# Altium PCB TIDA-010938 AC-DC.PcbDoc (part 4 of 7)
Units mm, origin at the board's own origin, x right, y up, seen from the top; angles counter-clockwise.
Board outline 275 x 170 mm, 4 copper layers (Top Layer, Layer 1, Layer 2, Bottom Layer), stack 1.787 mm thick; 711 components, 426 nets, 2196 pads, 1444 vias.
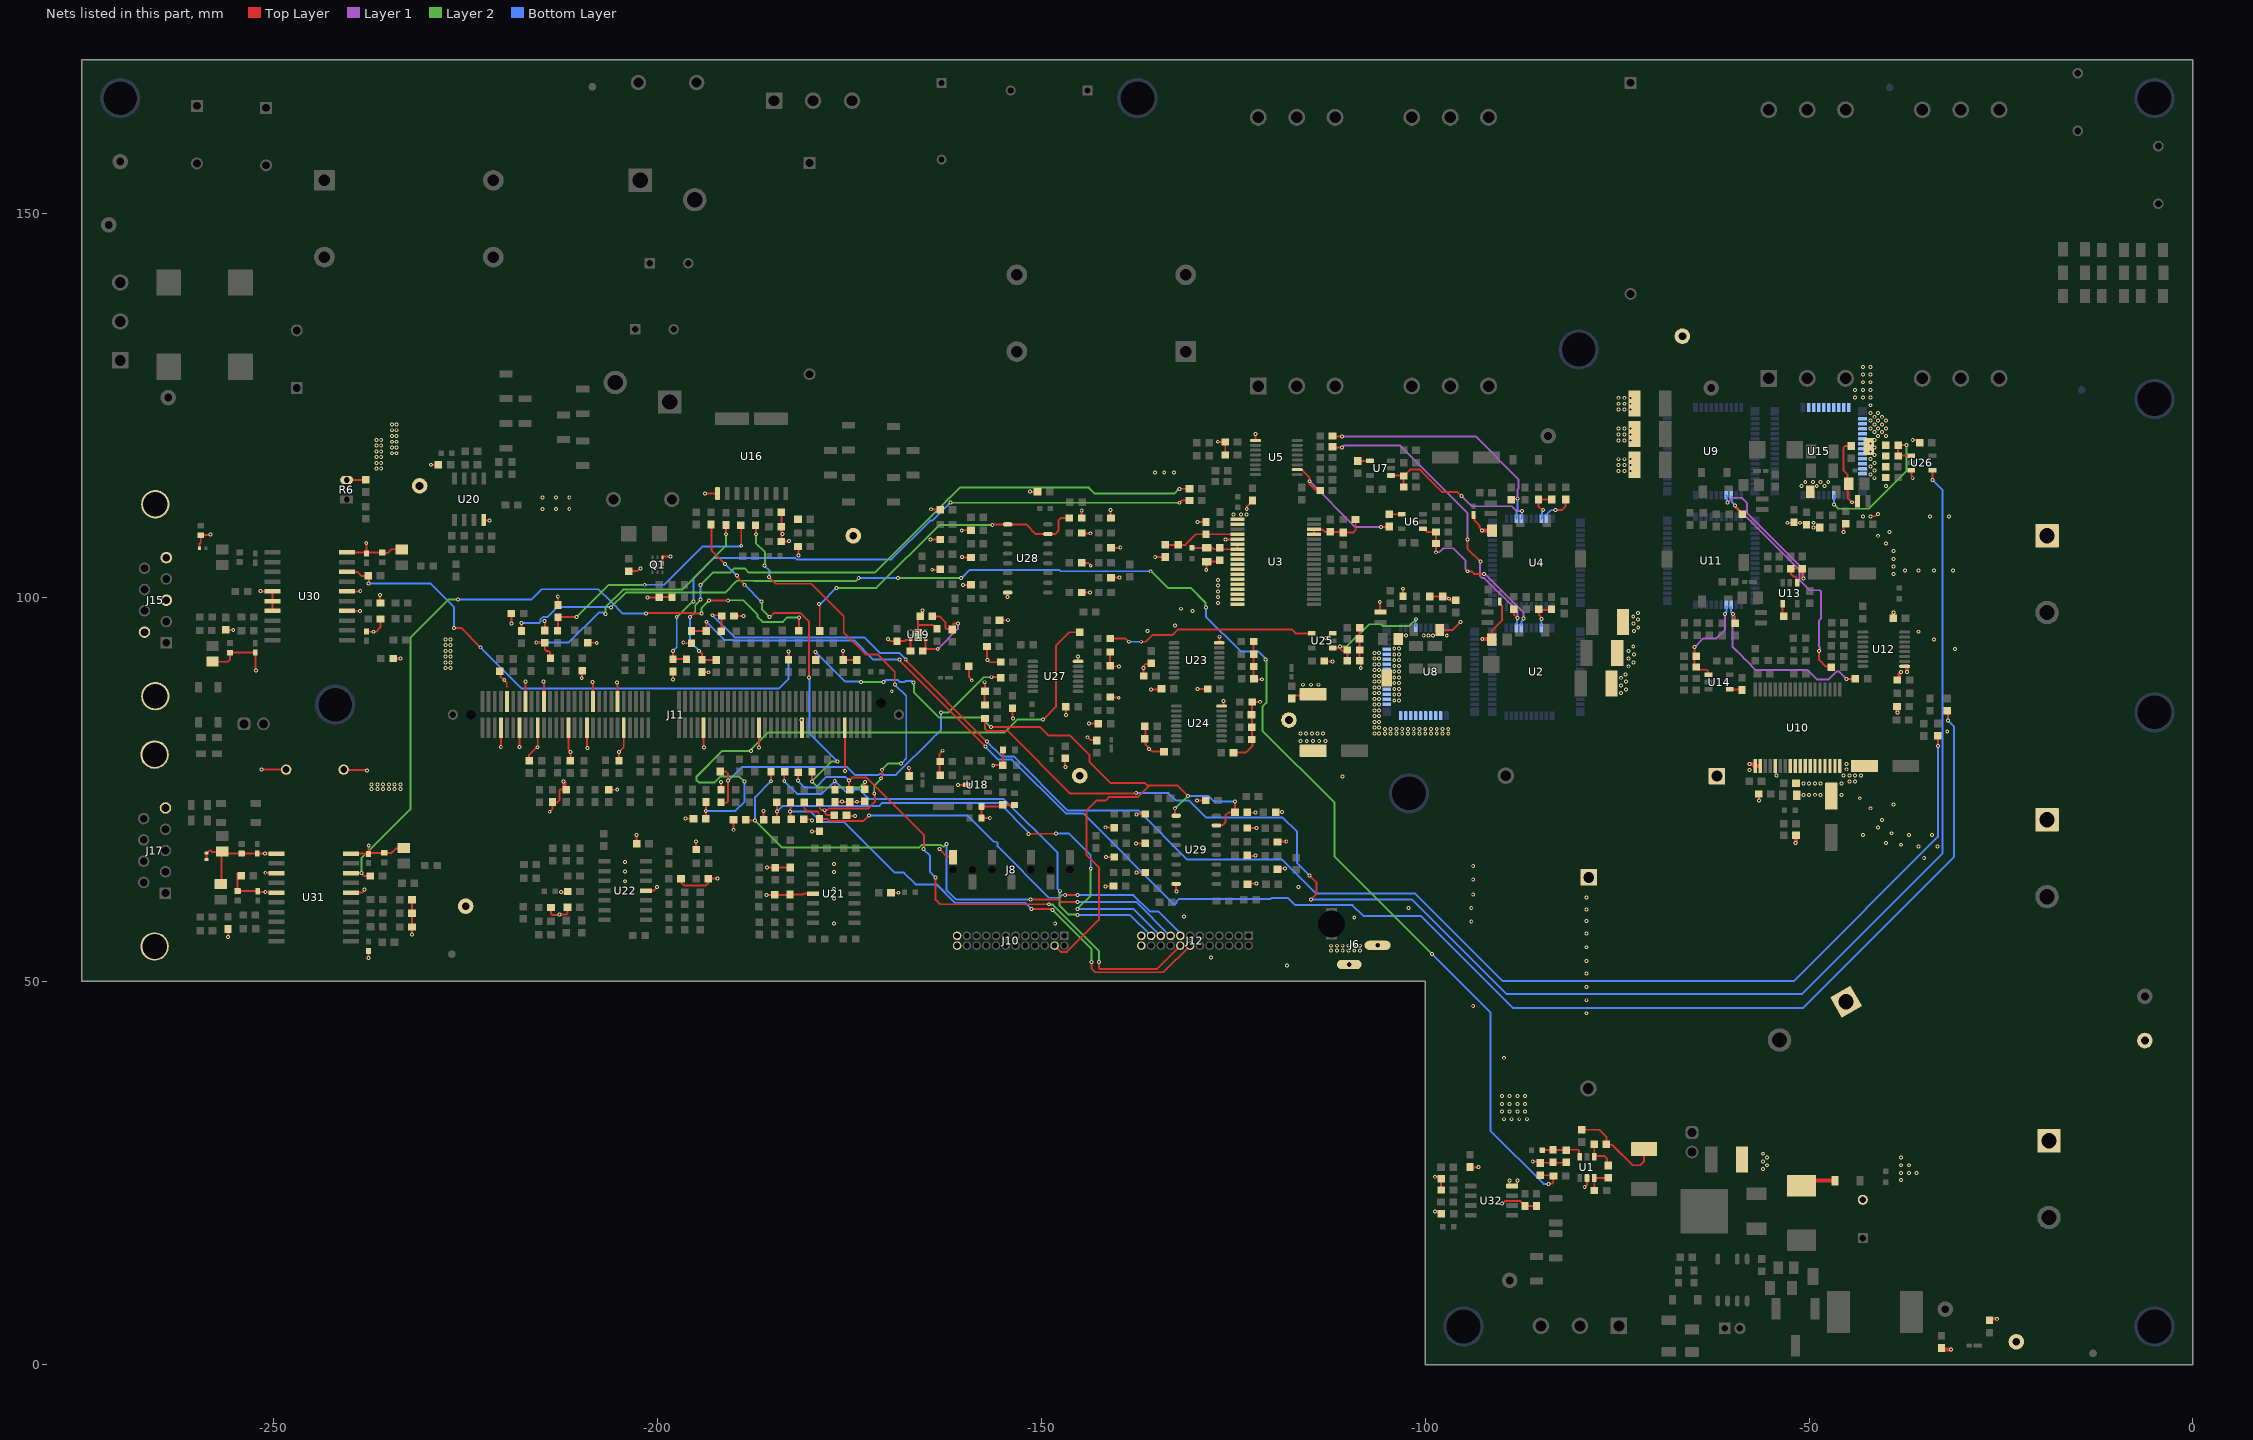
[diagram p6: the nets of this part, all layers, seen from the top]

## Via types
v1: diameter 0.508, hole 0.254, Top Layer to Bottom Layer, tented both sides, 1436 vias
v2: diameter 0.508, hole 0.254, Top Layer to Bottom Layer, 6 vias
v3: diameter 0.5, hole 0.2, Top Layer to Bottom Layer, 2 vias

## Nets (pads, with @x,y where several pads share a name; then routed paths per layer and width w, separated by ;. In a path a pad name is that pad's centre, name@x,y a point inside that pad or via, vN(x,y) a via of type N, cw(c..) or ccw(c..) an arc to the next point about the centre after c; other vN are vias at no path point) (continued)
"DC Bus-": C1.2 C2.1 C3.1 C4.1 C5.1 C6.2 C7.2 C9.1 C10.2 C18.1 C22.2 C23.1 C29.1 C30.2 C31.2 C36.1 C37.1 C38.2 C41.1 C42.1 C46.2 C49.2 C50.1 C51.1 C52.1 C53.1 C54.2 C55.2 C56.1 C64.1 C67.2 C68.1 C74.1 C76.2 C82.1 C83.1 C84.2 C86.1 C87.1 C88.2 C90.2 C92.1 C93.1 C94.2 C95.1 C96.1 C97.1 C98.1 C99.2 C100.1 C101.1 C105.2 C107.1 C108.1 C109.2 C110.2 C111.2 C112.1 C113.1 C114.2 C115.2 C118.2 C119.2 C120.2 C121.2 C122.2 C123.2 C124.2 C125.1 C126.2 C127.1 C128.1 C130.1 C131.1 C132.1 C133.1 C134.1 C135.1 C136.1 C137.1 C138.1 C139.1 C140.1 C141.1 C142.1 C145.1 C146.1 C150.2 C151.1 C152.1 C156.2 C157.1 C158.1 C161.1 C162.2 C163.1 C164.1 C165.1 C167.1 C168.1 C169.2 C170.1 C171.1 C172.1 C173.1 C174.1 C175.1 C176.2 C177.1 C178.1 C179.1 C180.1 C181.1 C182.2 C185.2 C186.2 C187.1 C189.1 C190.1 C191.2 C192.1 C193.1 C194.1 C195.2 C196.1 C197.2 C199.1 C200.1 C201.2 C202.1 C203.2 C204.1 C206.1 C208.1 C209.1 C214.1 C215.2 C216.2 C218.1 C219.1 C222.2 C229.2 C230.1 C231.1 C232.1 C234.1 C235.1 C238.2 C239.2 C241.1 C242.1 C251.2 C252.2 C253.1 C254.1 C255.1 C256.1 D19.2 D20.2 J6.2 J6.3 J8.7 J10.23 J10.24 J11.7 J11.10 J11.13 J11.16 J11.19 J11.22 J11.29 J11.35 J11.38 J11.46 J11.47 J11.65 J11.83 J11.97 J11.111 J12.23 J12.24 L5.1 L9.1 Q1.4 Q1.7 R1.2 R4.1 R6.2 R14.1 R16.1 R40.1 R43.1 R48.1 R50.2 R70.1 R74.1 R76.1 R90.2 R92.1 R100.2 R101.1 R102.1 R106.2 R107.1 R110.2 R115.1 R135.2 R147.1 R157.1 R167.1 R172.2 R177.1 R202.1 R252.1 R253.1 R254.1 R255.1 R256.1 R258.1 R297.1 R298.1 R299.1 R300.1 R301.1 R302.1 R303.1 R304.1 R305.1 R306.1 R307.1 R308.1 R335.1 R336.1 R337.1 R338.1 TP2.1 TP3.1 TP6.1 TP8.1 TP9.1 TP11.1 TP12.1 TP16.1 TP21.1 TP22.1 U1.2 U3.1 U3.2 U3.5 U3.8 U3.9 U3.10 U3.11 U3.12 U3.13 U3.14 U3.15 U3.16 U3.17 U3.18 U5.9 U8.18 U8.19 U8.20 U8.21 U8.22 U8.23 U8.24 U8.25 U8.26 U8.28 U8.29 U8.30 U8.31 U8.32 U8.33 U8.34 U8.35 U8.36 U8.37 U8.38 U8.39 U10.1 U10.2 U10.5 U10.8 U10.9 U10.10 U10.11 U10.12 U10.13 U10.14 U10.15 U10.16 U10.17 U10.18 U12.9 U15.18 U15.19 U15.20 U15.21 U15.22 U15.23 U15.24 U15.25 U15.26 U15.28 U15.29 U15.30 U15.31 U15.32 U15.33 U15.34 U15.35 U15.36 U15.37 U15.38 U15.39 U16.3 U18.2 U19.3 U19.7@-166.06,95.076 U20.4 U21.11 U22.11 U23.8 U24.8 U25.3 U26.3 U27.7 U28.8 U29.8 U30.4 U30.6 U30.10 U31.6 U31.10 U32.4 | length 355.8
  Top Layer w0.25: C1.2@-240.916,77.54 -240.85,77.474 -237.899,77.474 v1(-237.85,77.425) ; R6.2@-240.5,115.27 -238.03,115.27 C10.2@-238,115.3 ; U30.4@-240.456,98.222 -238.903,98.222 v1@-238.9,98.225 ; U30.6@-240.456,100.762 -238.838,100.762 v1@-238.8,100.8 ; U30.10@-240.456,105.842 -238.078,105.842 C195.2@-237.916,105.68 ; U31.6@-239.92,61.519 -238.481,61.519 v1@-238.1,61.9 ; U31.10@-239.92,66.599 -237.693,66.599 C216.2@-237.658,66.564 ; C197.2@-237.975,95.4 -237.875,95.5 -236.675,95.5 -236.1,96.075 ; v1@-237.925,107.1 -237.916,107.091 C195.2@-237.916,105.68 ; v1@-237.675,53.025 -237.658,53.042 C222.2@-237.658,53.934 ; v1@-237.675,67.525 -237.658,67.508 C216.2@-237.658,66.564 ; v1@-236.175,100.15 -236.175,99.309 C219.1@-236.1,99.234 ; C218.1@-236.1,97.169 -236.075,97.144 -236.075,96.125 ; C189.1@-236.075,105.875 -236.133,105.817 -237.779,105.817 C195.2@-237.916,105.68 ; C189.1@-235.873,105.817 -235.806,105.75 -235.175,105.75 -234.675,106.25 C191.2@-233.6,106.25 ; C214.1@-235.676,66.701 -237.521,66.701 C216.2@-237.658,66.564 ; C214.1@-235.615,66.701 -235.564,66.65 -234.675,66.65 -234.075,67.25 C215.2@-233.075,67.25 ; R50.2@-234.45,92 v1(-233.5,92) ; v1@-232,56.1 -231.99,56.11 C235.1@-231.99,57.041 ; C235.1@-231.99,57.16 C232.1@-231.99,58.819 C234.1@-231.99,60.597 ; v1(-229.5,117.25) C230.1@-228.55,117.25 ; U20.4@-222.645,109.675 U20.4@-222.645,109.825 ; U20.4@-222.645,110.075 U20.4@-222.645,109.825 ; v1(-221.9,110) -222.47,110 U20.4@-222.645,109.825 ; C133.1@-220.565,90.339 -220.435,90.209 -220.435,89.61 -219.65,88.825 -219.65,88.325 ; v1@-220.425,80.55 -220.407,80.568 J11.7@-220.407,82.998 ; C146.1@-219.05,97.875 -219.05,96.675 v1@-219.025,96.65 ; J11.13@-218.007,82.998 -218.007,80.482 v1@-218,80.475 ; v1@-217.225,88.9 -217.207,88.882 J11.16@-217.207,86.398 ; C152.1@-216.725,78.7 -216.725,79.475 -215.799,80.401 -215.744,80.401 -215.7,80.445 v1@-215.7,80.5 ; v1@-215.607,80.507 J11.19@-215.607,82.998 ; J11.22@-214.807,86.398 -214.807,88.918 v1@-214.8,88.925 ; C112.1@-214.698,95.672 -214.675,95.695 v1@-214.675,96.825 ; v1(-214.05,72.05) -214.05,72.075 -213.675,72.45 C158.1@-213.675,73.325 -213.6,73.25 -213.096,73.25 -212.8,73.546 -212.8,74.8 -212.65,74.95 C145.1@-212.25,74.95 ; R147.1@-213.873,59.576 -213.873,58.771 -213.727,58.625 -213.42,58.625 ; -213.419,58.626 v1@-212.925,58.626 ; C107.1@-212.975,98.975 -213,99 -213,100.075 v1@-212.975,100.1 ; v1(-212.8,58.675) -211.871,58.675 -211.725,58.821 -211.725,59.268 -211.6,59.393 C150.2@-211.6,59.425 ; v1@-212.6,61.525 -211.821,61.525 C142.1@-211.696,61.65 ; J11.29@-211.607,82.998 -211.607,80.177 -211.325,79.895 v1@-211.325,79.85 ; C157.1@-211.363,78.701 v1@-211.363,79.825 ; v1@-209.854,89.46 -209.854,90.371 C132.1@-209.8,90.425 ; J11.35@-209.207,82.998 -209.207,80.482 v1@-209.2,80.475 ; C134.1@-209.099,94.07 -207.97,94.07 v1@-207.95,94.05 ; J11.38@-208.407,86.398 -208.407,88.893 v1@-208.4,88.9 ; C151.1@-206.375,74.916 -205.334,74.916 v1@-205.325,74.925 ; J11.46@-205.207,86.398 -205.207,88.793 v1@-205.2,88.8 ; C164.1@-205.013,78.701 -205,78.714 v1@-205,79.8 ; v1@-204.95,79.925 -204.925,79.925 -204.407,80.443 J11.47@-204.407,82.998 ; C105.2@-203.75,103.4 -202.67,103.4 -202.32,103.75 v1(-202.25,103.75) ; C165.1@-202.718,67.871 -202.718,68.882 v1@-202.7,68.9 ; U22.11@-201.504,61.775 -200.475,61.775 v1@-200.05,62.2 ; v1(-201.3,99.975) -199.8,99.975 C114.2@-199.775,100 R90.2@-198.225,100 ; Q1.7@-199.35,104.345 Q1.4@-199.35,105.2 ; Q1.4@-199.35,105.225 -199.35,105.25 -199.325,105.275 v1@-198.3,105.275 ; R90.2@-198.175,100.05 R90.2@-198.125,100 ; v1(-198,89.275) -197.997,89.278 C37.1@-197.997,90.326 ; C163.1@-196.937,63.32 -196.9,63.283 -196.9,62.771 -196.579,62.45 -193.7,62.45 -193.45,62.7 -193.45,63.05 R172.2@-193.475,63.075 ; v1@-196.675,94.075 -196.598,93.998 C83.1@-195.582,93.998 ; v1@-196.325,71.15 -196.309,71.134 C56.1@-195.316,71.134 ; C161.1@-194.981,67.13 -194.981,68.169 v1@-194.975,68.175 ; C36.1@-194.2,90.25 -194.174,90.224 v1(-193.359,90.224) ; J11.65@-194.007,82.998 -194.007,80.457 v1@-194,80.45 ; v1(-193.8,113.5) -192.211,113.5 U16.3@-192.195,113.516 ; R172.2@-193.381,63.32 -193.326,63.375 v1@-192.225,63.375 ; v1@-191.775,75.85 -191.75,75.825 C92.1@-191.75,74.9 ; v1(-190.1,69.7) C136.1@-190.1,71 ; C82.1@-190.05,97.55 -190.025,97.575 v1(-188.825,97.575) ; v1@-186.825,80.425 -186.807,80.443 J11.83@-186.807,82.998 ; v1(-186.2,72.125) -186.2,71.25 C137.1@-186.175,71.225 ; v1@-185.8,64.8 -185.781,64.781 -182.781,64.781 C156.2@-182.725,64.725 ; v1@-185.75,61.275 -185.75,61.244 -185.706,61.2 -182.805,61.2 C162.2@-182.738,61.267 -181.058,61.267 -180.925,61.4 -180.325,61.4 U21.11@-180.3,61.425 ; C111.2@-183.89,107.263 -182.988,107.263 v1@-182.975,107.25 ; C111.2@-183.877,107.373 C109.2@-183.877,111.051 ; v1(-181.65,105.45) -181.65,106.5 C115.2@-181.525,106.625 ; v1(-181.25,84) -181.228,83.978 -181.228,83.019 J11.97@-181.207,82.998 ; C130.1@-180.975,71.075 -180.145,71.075 -179.97,70.9 v1(-179.9,70.9) ; v1(-179.9,69.5) C135.1@-178.9,69.5 ; C231.1@-176.9,73.325 v1@-175.95,73.325 ; v1@-175.975,73.35 v1@-175.95,73.325 ; v1(-175.825,93) -175.825,92 C182.2@-175.775,91.95 ; C182.2@-175.775,91.826 -174.251,91.826 C181.1@-174.151,91.726 ; v1@-175.675,77.425 -175.66,77.425 -175.591,77.494 -175.591,82.982 J11.111@-175.607,82.998 ; C108.1@-175.4,71.6 -175.3,71.5 v1(-174.3,71.5) ; v1@-174.025,73.325 C131.1@-174.975,73.325 v1@-175.95,73.325 ; v1(-174.025,73.35) -173.35,73.35 C113.1@-173.3,73.4 ; v1@-169.9,94.5 -169.675,94.275 C123.2@-168.8,94.275 -167.825,94.275 -167.65,94.45 U19.3@-167.035,94.45 ; C141.1@-169.595,61.512 -169.583,61.5 v1(-168.6,61.5) ; R70.1@-167.2,76.7 v1@-167.2,77.8 ; C29.1@-167.05,93 -167.035,93.015 U19.3@-167.035,94.426 ; v3(-166.06,95.626) -166.06,96.368 ; v1(-165.5,98.25) -165.5,97.8 R16.1@-165.8,97.5 -166.06,97.24 -166.06,96.368 ; v1@-164.4,107.525 -164.397,107.522 R301.1@-163.185,107.522 ; v1@-164.375,111.4 -164.37,111.405 R302.1@-163.185,111.405 ; v1@-164.2,103.575 -163.249,103.575 R300.1@-163.185,103.639 ; C122.2@-163.596,95.876 -163.596,95.901 -163.946,96.251 -163.971,96.251 -164.088,96.368 -166.06,96.368 ; v1@-163.2,67.1 -162.3,66.2 J8.7@-161.24,66.2 ; C127.1@-163.197,76.819 -163.25,76.872 -163.25,79.58 -162.9,79.93 v1(-162.9,80) ; v1@-160.85,75.525 -160.826,75.549 U18.2@-159.708,75.549 ; v1@-160.35,105.15 -160.331,105.169 C194.1@-159.175,105.169 ; v1@-160.35,108.725 C192.1@-159.175,108.725 ; v1(-160.225,101.6) -159.188,101.6 C196.1@-159.175,101.613 ; R76.1@-159.45,91 -159.45,89.62 -159.075,89.245 v1(-159.075,89.175) ; R258.1@-157.425,87.745 -157.425,86.052 C187.1@-157.341,85.967 ; v1@-157.4,88.95 -157.341,88.891 R258.1@-157.341,87.745 ; C101.1@-157.087,93.587 -157.087,91.956 -157,91.87 v1(-157,91.8) -156.93,91.8 -156.655,91.525 -155.525,91.525 R256.1@-155.425,91.425 ; v1@-156.825,71.25 -156.844,71.231 C124.2@-157.812,71.231 C120.2@-157.812,72.755 -155.27,72.755 C125.1@-155.05,72.975 ; v1@-156.2,78.1 -156.173,78.127 R106.2@-155.03,78.127 C126.2@-155.03,80.055 ; C98.1@-155.45,97 -154.325,97 v1@-154.3,96.975 ; C126.2@-155.075,80.166 C126.2@-155.03,80.121 ; C125.1@-155.03,72.971 -154.984,72.925 -153.55,72.925 C121.2@-153.425,72.8 ; v1(-154.4,100.032) U28.8@-154.4,100.605 ; C55.2@-153.76,85.543 -153.76,84.16 v1@-153.75,84.15 ; v1@-151.525,113.75 -151.498,113.723 C201.2@-150.5,113.723 ; v1@-146.9,77.9 R101.1@-146.9,79 ; v1@-146.825,84.7 -146.81,84.715 C93.1@-146.81,85.738 ; v1(-145.25,92.25) -145.25,91.664 U27.7@-145.219,91.633 ; C200.1@-144.753,100.604 -143.679,100.604 v1(-143.675,100.6) ; C204.1@-144.753,104.487 -144.741,104.475 -143.878,104.475 -143.624,104.221 -143.624,104.145 v1(-143.575,104.096) ; C206.1@-144.753,108.37 -144.683,108.3 v1@-143.675,108.3 ; R254.1@-144.753,110.312 -144.753,111.272 v1@-144.725,111.3 ; v1(-144,81.75) -143.983,81.75 -143.633,81.4 -142.845,81.4 R102.1@-142.783,81.338 ; v1@-143.725,83.5 -143.7,83.525 C52.1@-142.575,83.525 ; v1@-141.65,62.35 -140.643,62.35 R306.1@-140.607,62.386 ; v1@-141.6,66.15 -141.591,66.159 R307.1@-140.531,66.159 ; v1@-141.6,70.025 -140.587,70.025 R308.1@-140.531,69.969 ; R252.1@-141.046,87.008 -140.962,86.925 v1@-139.925,86.925 ; R255.1@-141.046,91.072 -140.973,91 v1@-139.75,91 ; C100.1@-141.046,92.85 -141.046,91.321 R255.1@-141,91.275 ; R299.1@-141,102.601 R299.1@-140.943,102.544 -139.906,102.544 v1@-139.9,102.55 ; v1@-141,111.35 -141,110.367 R297.1@-140.943,110.31 ; R298.1@-140.943,106.427 -139.773,106.427 v1(-139.725,106.475) ; v1@-137.65,67.9 -137.613,67.937 C193.1@-136.467,67.937 ; v1@-137.6,64.125 -137.598,64.127 C199.1@-136.467,64.127 ; v1@-137.6,71.75 -137.597,71.747 C190.1@-136.467,71.747 ; C172.1@-136.675,89.725 -136.675,91.025 -136.4,91.3 -135.9,91.3 C173.1@-135.8,91.4 ; C180.1@-136.525,83.175 -136.425,83.075 -136.425,80.75 -135.55,79.875 -134.775,79.875 C176.2@-134.025,79.875 ; v1(-135.7,88) C169.2@-134.625,88 ; v1@-135.075,105.25 -135.05,105.225 R14.1@-133.875,105.225 ; v1@-132.45,61.6 U29.8@-132.45,62.645 ; v1@-129.775,73.45 -129.721,73.504 C203.2@-128.593,73.504 ; v1@-129.625,88.025 -128.375,88.025 C171.1@-128.35,88.05 ; v1@-129.6,109.8 C23.1@-128.55,109.8 ; v1@-128.5,103.7 -128.475,103.725 C18.1@-128.475,104.625 -127.125,104.625 -127,104.75 C22.2@-127,104.9 ; v1@-127.1,120.2 -127.075,120.225 C42.1@-126.05,120.225 -126.05,118.75 C41.1@-126.1,118.7 ; U23.8@-126.825,94.05 v1@-126.825,94.875 ; U24.8@-126.525,85.825 -126.433,85.917 -126.298,85.917 v1(-126.298,86.452) ; v1(-126,107.5) -125.975,107.525 -124.475,107.525 U3.5@-124.45,107.55 ; C178.1@-124.975,79.75 -123.375,79.75 -122.525,80.6 C177.1@-122.525,81.5 ; v1(-123.25,111.5) -123.201,111.549 -123.201,111.874 -122.5,112.575 C38.2@-122.5,112.6 ; C208.1@-123.183,66.38 -123.103,66.3 v1@-122.175,66.3 ; C209.1@-123.183,69.936 -123.172,69.925 v1(-122,69.925) ; R253.1@-123.183,72.001 -123.107,71.925 v1@-122.15,71.925 ; C202.1@-123.145,62.618 -123.038,62.725 v1@-122.025,62.725 ; C177.1@-122.55,81.5 R202.1@-122.55,86.35 v1@-121.525,86.35 ; C170.1@-122.35,89.375 C167.1@-122.35,92.575 R177.1@-122.35,94.225 ; C170.1@-122.3,89.375 -122.225,89.3 v1@-121.1,89.3 ; U5.9@-122.125,120.423 -122.125,121.175 v1@-122.1,121.2 ; R303.1@-119.389,72.001 v1(-118.639,72.001) ; R304.1@-119.246,68.125 -119.171,68.2 v1(-118.1,68.2) ; R305.1@-119.165,64.65 v1@-118.225,64.65 ; R43.1@-117.4,86.8 -117.4,86.825 -117.05,87.175 -114.825,87.175 C238.2@-114.6,87.4 ; C185.2@-113.15,91.625 -113.125,91.6 v1(-112.1,91.6) ; v1(-112.945,94.671) -112.876,94.671 -112.473,95.074 -112.456,95.074 -112.251,95.279 U25.3@-112.051,95.279 ; C253.1@-108.562,93.125 C255.1@-108.562,94.604 R337.1@-108.562,95.804 ; C253.1@-108.55,93.125 R335.1@-108.55,91.725 -108.4,91.575 v1(-108.4,90.8) ; R337.1@-108.55,95.85 R337.1@-108.5,95.8 ; v1@-105.9,99.3 -105.9,98.15 L5.1@-105.825,98.075 ; C54.2@-103.209,94.55 -103.209,94.79 -102.999,95 v1(-102.5,95) ; C51.1@-102.9,100.125 v1(-102.9,101.1) ; R40.1@-99.4,100.1 C53.1@-97.7,100.1 -97.6,100 -97.1,100 v1(-96.9,99.8) -96.7,99.6 ; v1(-98.73,20) -98.225,20 C128.1@-97.9,19.675 ; v1(-98.73,24.5) -98.175,24.5 R135.2@-97.925,24.25 -97.925,22.8 C139.1@-97.975,22.75 ; C49.2@-98.1,95.725 -96.475,95.725 v1@-95.4,96.8 ; C50.1@-96.4,99.5 -96.6,99.5 -96.7,99.6 ; C50.1@-96.025,99.6 -96.7,99.6 ; C138.1@-94.175,25.775 -94.125,25.725 v1@-93.025,25.725 ; v1(-90,21) -89.93,21 -89.59,21.34 -87.615,21.34 -87,20.725 C74.1@-87,20.7 R110.2@-85.5,20.7 ; v1(-89,24) -89,23.48 -88.825,23.305 U32.4@-88.675,23.305 -88.213,23.305 -88.038,23.48 -88.038,23.962 v1(-88,24) ; v1(-86,26.5) -85.15,26.5 -84.975,26.325 C6.2@-82.05,26.325 ; C140.1@-79.65,30.675 C140.1@-79.6,30.625 -77.325,30.625 -76.375,29.675 R4.1@-76.375,29.15 ; v1@-79.15,23.2 -78.933,23.417 U1.2@-78.933,24.343 ; R4.1@-76.4,28.725 -76.346,28.671 -75.671,28.671 -73,26 -72,26 -71.5,26.5 R1.2@-71.5,28.1 ; C68.1@-56.575,74.35 -56.5,74.275 v1(-56.5,73.5) ; U10.5@-54.425,78.025 -54.325,77.925 -54.325,76.895 -54.25,76.82 v1(-54.25,76.75) ; v1(-52.8,109.7) -52.05,109.7 C95.1@-51.975,109.775 ; v1(-51.2,109.7) -50.575,109.7 C97.1@-50.325,109.45 ; C94.2@-50,114.425 -49.825,114.25 C94.2@-49.75,114.25 ; v1(-49.434,109.056) -48.644,109.056 R74.1@-48.625,109.075 ; v1(-45.5,108.5) -45.5,109.3 C96.1@-45.225,109.575 ; C99.2@-45,114.5 -45,112.952 v1(-44.415,112.367) -43.633,112.367 L9.1@-43.5,112.5 ; C99.2@-45,115 -45,116 -45.5,116.5 -45.5,119.5 -45.3,119.7 R115.1@-44.5,119.7 ; v1(-42,110.5) -41.955,110.545 -41.371,110.545 -41.07,110.846 v1(-41,110.846) ; U26.3@-36.675,116.55 -36.675,115.745 -36.5,115.57 v1(-36.5,115.5) ; v1(-36.5,120.5) -36.43,120.5 -36.38,120.45 -35.95,120.45 C186.2@-35.6,120.1
  Top Layer w0.5: v1(-212.25,76) -212.25,75.998 -212.121,75.869 -212.121,75.154 C145.1@-211.896,74.929 ; C229.2@-58.75,26.75 C229.2@-58.5,26.5 ; v1(-57.75,78.25) -57.4,78.25 -57.175,78.025 U10.1@-57.025,78.025 U10.2@-56.375,78.025 ; v1(-51.75,68) -51.75,68.002 -51.7,68.052 R48.1@-51.7,69 ; D20.2@-51,23.068 -50.068,24 D19.2@-46.637,24 ; C84.2@-39.05,97.25 -39.002,97.298 -39.002,97.998 v1(-39,98) ; C86.1@-38.55,85.75 -38.502,85.702 -38.502,85.002 v1(-38.5,85) ; C87.1@-38.5,89.2 -38.475,89.2 -38.25,89.425 -38.25,89.998 -38,90.248 v1(-38,90.25) ; U12.9@-37.55,91 -37.302,91 -37.252,90.95 -37.252,90.252 v1(-37.25,90.25) ; C119.2@-32.75,2.2 -32.552,2.002 -31.502,2.002 v1(-31.5,2) ; R100.2@-26.5,5.8 -26.302,5.998 -25.502,5.998 v1(-25.5,6)
  other v1: -79.225,23.175 -38,24.1 -38,25 -37,25 -36,25 -56,25.5 -93.05,25.775 -55.5,26 -38,26 -37,26 -56,26.5 -55.5,27 -38,27 -56,27.5 -89.75,32 -88.75,32 -87.75,32 -86.75,32 -90,33 -89,33 -88,33 -87,33 -90,34 -89,34 -88,34 -87,34 -90,35 -89,35 -88,35 -87,35 -89.75,40 -79,45.8 -93.75,46.75 -79,47.5 -79,49.2 -79,51 -118.004,52.005 -79,52.6 -237.65,53.025 -127.906,53.052 -112.25,54 -111.5,54 -110.75,54 -110,54 -109.25,54 -108.5,54 -79,54.4 -112.25,54.6 -111.5,54.6 -110.75,54.6 -110,54.6 -109.25,54.6 -108.5,54.6 -231.975,56.05 -79,56.2 -177,57.471 -148.2,57.5 -94,57.75 -79,57.8 -109.25,58.25 -131.4,58.4 -79,59.3 -102.195,59.488 -94,59.5 -177,60.75 -79,60.9 -185.825,61.2 -93.75,61.25 -212.575,61.575 -132.425,61.675 -238.174,61.917 -177,62 -200.075,62.225 -116.5,62.25 -141.65,62.325 -122,62.725 -204.25,63 -93.75,63.25 -192.2,63.35 -137.625,64.125 -176.997,64.223 -204.25,64.25 -118.25,64.675 -185.725,64.775 -93.75,65 -177,65.25 -204.25,65.5 -35,66 -141.6,66.175 -122.125,66.35 -163.298,67.174 -35.75,67.5 -33.25,67.5 -237.625,67.675 -38,67.75 -137.675,67.925 -40,68 -194.975,68.15 -43,69 -37,69 -34,69 -202.75,69.025 -39.25,69.25 -41,70 -141.65,70.025 -40.5,71 -196.375,71.15 -156.725,71.25 -137.625,71.7 -122.125,71.95 -42,72.5 -39,73 -176,73.375 -129.75,73.5 -43.396,73.803 -50.75,74.25 -50,74.25 -48.5,74.25 -45.75,74.25 -49.239,74.26 -205.25,74.925 -237.25,75 -236.5,75 -235.75,75 -235,75 -234.25,75 -233.5,75 -160.875,75.55 -237.25,75.6 -236.5,75.6 -235.75,75.6 -235,75.6 -234.25,75.6 -233.5,75.6 -50.75,75.75 -50,75.75 -49.25,75.75 -48.5,75.75 -45.75,75.75 -191.75,75.95 -44.75,76 -44,76 -110.779,76.629 -45.5,76.75 -44.75,76.75 -44,76.75 -43.25,76.75 -175.575,77.375 -57.75,77.5 -45.145,77.581 -167.275,77.775 -146.875,77.875 -156.275,78.075 -45.145,78.25 -211.325,79.825 -205,79.85 -135.975,80.225 -209.15,80.35 -193.975,80.4 -186.8,80.425 -215.625,80.45 -220.425,80.475 -217.975,80.475 -116.25,81.25 -115.438,81.25 -114.625,81.25 -113.813,81.25 -113,81.25 -116.25,82.25 -115.513,82.25 -114.775,82.25 -114.038,82.25 -113.3,82.25 -106.6,82.25 -106,82.25 -105.25,82.25 -104.5,82.25 -103.75,82.25 -103,82.25 -102.25,82.25 -101.5,82.25 -100.75,82.25 -100,82.25 -99.25,82.25 -98.5,82.25 -97.75,82.25 -97,82.25 -32,82.5 -105.25,82.85 -104.5,82.85 -103.75,82.85 -103,82.85 -102.25,82.85 -101.5,82.85 -100.75,82.85 -100,82.85 -99.25,82.85 -98.5,82.85 -97.75,82.85 -97,82.85 -106.6,83 -106,83 -143.775,83.525 -106.6,83.75 -106,83.75 -153.725,84.2 -106.6,84.5 -106,84.5 -146.775,84.675 -106.6,85.25 -106,85.25 -106.6,86 -106,86 -121.5,86.375 -104.036,86.55 -103.436,86.55 -106.6,86.75 -106,86.75 -139.925,86.9 -104.036,87.3 -103.436,87.3 -106.6,87.5 -106,87.5 -74.5,87.5 -169.5,87.75 -73.825,88 -129.65,88.025 -104.036,88.05 -103.436,88.05 -106.6,88.25 -106,88.25 -74.5,88.5 -115.9,88.6 -114.9,88.6 -113.9,88.6 -104.036,88.8 -103.436,88.8 -205.275,88.875 -157.4,88.925 -208.475,88.975 -214.835,88.995 -106.6,89 -106,89 -73.85,89 -217.185,89.02 -219.975,89.225 -121.245,89.312 -209.879,89.46 -74.5,89.5 -104.036,89.55 -103.436,89.55 -106.6,89.75 -106,89.75 -73.925,89.925 -104.036,90.3 -103.436,90.3 -106.6,90.5 -106,90.5 -227.6,90.75 -227,90.75 -136.7,90.8 -139.875,90.975 -73.5,91 -104.036,91.05 -103.436,91.05 -106.6,91.25 -106,91.25 -72.875,91.475 -227.6,91.5 -227,91.5 -104.036,91.8 -103.436,91.8 -106.6,92 -106,92 -73.5,92 -227.6,92.25 -227,92.25 -72.8,92.525 -104.036,92.55 -103.436,92.55 -106.6,92.75 -106,92.75 -227.6,93 -227,93 -73.5,93 -31,93.25 -104.036,93.3 -103.436,93.3 -72.9,93.575 -227.6,93.75 -227,93.75 -207.925,94.05 -196.65,94.075 -227.6,94.5 -227,94.5 -33.75,94.5 -169.975,94.575 -126.825,94.85 -100.2,95 -99.6,95 -99,95 -97.2,95 -237.025,95.5 -35.75,95.5 -72.825,95.575 -136.2,95.6 -72.25,96.05 -132.6,96.3 -72.85,96.55 -219.042,96.576 -95.425,96.75 -214.725,96.875 -154.375,97 -72.275,97.075 -72.9,97.5 -72.3,97.95 -130.3,98.2 -238.775,98.225 -131.8,98.5 -127,99.25 -105.925,99.35 -127,100 -213,100.1 -236.175,100.275 -127,100.75 -238.725,100.8 -127,101.5 -127,102.25 -139.85,102.575 -39,103 -37.5,103.5 -35.75,103.5 -33.75,103.5 -31.25,103.5 -128.525,103.55 -164.225,103.575 -39,104 -39,105 -160.35,105.225 -135.175,105.25 -198.325,105.3 -39,106 -40,107 -237.95,107.075 -182.9,107.3 -164.425,107.525 -41,108 -183.75,108.25 -143.625,108.325 -39.5,108.5 -160.375,108.7 -49.434,109.7 -129.675,109.775 -43,110.5 -34.25,110.5 -31.75,110.5 -125,110.75 -124,110.75 -123.275,110.75 -144.75,111.275 -141,111.375 -164.4,111.45 -215,111.5 -213.25,111.5 -211.5,111.5 -215,113 -213.25,113 -211.5,113 -151.5,113.75 -51,114.5 -49,114.5 -48,114.5 -40,114.5 -50.5,115 -49.5,115 -48.5,115 -47.5,115 -41.5,115.5 -42,116 -135.189,116.247 -134,116.25 -132.75,116.25 -74.825,116.425 -74.05,116.425 -73.275,116.425 -41.5,116.5 -236.6,116.75 -236,116.75 -42,117 -74.825,117.2 -74.05,117.2 -73.275,117.2 -236.6,117.5 -236,117.5 -41.5,117.5 -74.825,117.975 -74.05,117.975 -73.275,117.975 -42,118 -236.6,118.25 -236,118.25 -41.5,118.5 -234.6,118.75 -234,118.75 -236.6,119 -236,119 -42,119 -234.6,119.5 -234,119.5 -41.5,119.5 -236.6,119.75 -236,119.75 -42,120 -234.6,120.25 -234,120.25 -127.025,120.25 -74.825,120.425 -74.05,120.425 -73.275,120.425 -236.6,120.5 -236,120.5 -41.5,120.5 -234.6,121 -234,121 -41,121 -40,121 -74.825,121.2 -74.05,121.2 -73.275,121.2 -122.125,121.25 -41.5,121.5 -40.5,121.5 -234.6,121.75 -234,121.75 -74.825,121.975 -74.05,121.975 -73.275,121.975 -42,122 -41,122 -40,122 -234.6,122.5 -234,122.5 -41.5,122.5 -40.5,122.5 -42,123 -41,123 -40,123 -41.5,123.5 -40.5,123.5 -42,124 -41,124 -74.825,124.425 -74.05,124.425 -73.275,124.425 -42,125 -74.825,125.2 -74.05,125.2 -73.275,125.2 -74.825,125.975 -74.05,125.975 -73.275,125.975 -44,126 -43,126 -42,126 -44,127 -43,127 -42,127 -43,128 -42,128 -43,129 -42,129 -43,130 -42,130
  other v3: -166.06,94.526
Enable_Buffer_ACDC: R232.2 R254.2 U28.1 U28.15 | length 42.1
  Top Layer w0.25: v1(-178.996,99.095) -178.996,99.025 -178.876,98.906 R232.2@-178.876,95.598 ; v1(-156.4,109.4) -156.352,109.448 -154.448,109.448 U28.1@-154.4,109.495 -151.995,109.495 -150.725,108.225 -149.525,108.225 U28.15@-149.5,108.2 ; U28.15@-149.15,108.225 -148.175,108.225 -147.775,108.625 -147.775,109.95 -147.4,110.325 -146.675,110.325 R254.2@-146.625,110.375
  Layer 2 w0.25: v1(-176.674,101.217) -171.483,101.217 -163.3,109.4 v1(-156.4,109.4)
  Bottom Layer w0.25: v1(-178.996,99.095) -178.946,99.145 -178.764,99.145 -176.709,101.2 v1@-176.6,101.2
Enable_Buffer_DCDC: J10.4 R230.2 R253.2 U29.1 U29.15 | length 105.6
  Top Layer w0.25: v1(-179.425,92.85) v1@-179.425,92.92 ; v1@-179.4,92.8 -179.4,91.842 R230.2@-179.384,91.826 ; v1@-156.5,83.1 -150.218,83.1 -149.118,82 -146.3,82 -143.733,79.433 -143.733,78.524 -141.008,75.8 -136.554,75.8 -136.208,75.454 -135.923,75.454 ; J10.4@-148.285,54.62 -147.45,53.785 -146.669,53.785 -142.5,57.954 -142.5,64.802 -144.1,66.402 -144.1,72.25 -142.85,73.5 -141.648,73.5 -141.202,73.946 -137.431,73.946 -135.923,75.454 ; v1@-132.575,72.425 -132.575,71.66 U29.1@-132.45,71.535 ; v1@-131,74.2 -132.254,75.454 -135.923,75.454 ; U29.15@-127.2,70.265 -127.143,70.322 -126.353,70.322 -126.025,70.65 -126.025,71.575 -125.625,71.975 R253.2@-124.925,71.975 ; R253.2@-124.783,72.001 v1@-124.783,73.333
  Layer 2 w0.25: v1(-173.475,88.975) -170.625,88.975 v1@-170.6,89 ; v1@-166.6,88.9 -166.6,87.6 -163.346,84.346 -157.846,84.346 v1(-156.575,83.075) ; v1(-132.6,72.5) -132.563,72.5 -130.963,74.1 v1(-130.925,74.1)
  Bottom Layer w0.25: v1(-179.425,92.85) -175.575,89 v1@-173.4,89 ; v1(-170.575,88.975) -170.537,88.975 -170.3,89.213 -168.707,89.213 -168.469,88.975 -167.786,88.975 -167.657,89.104 -166.974,89.104 -166.77,88.9 v1@-166.7,88.9 ; v1@-130.9,74.1 -128.222,74.1 -127.522,73.4 v1(-124.775,73.4)
  other v1: -166.675,88.875
Enable_CAN: R224.2 R310.1 U30.8 | length 70.8
  Top Layer w0.25: U30.8@-240.456,103.302 -239.098,103.302 -238.546,102.75 R310.1@-237.975,102.75 ; R310.1@-237.7,102.794 -237.6,102.694 v1@-237.6,101.7 ; v1(-226.5,96) -225.6,96 v1@-223.1,93.5 ; R224.2@-182.94,91.864 -182.9,91.904 v1@-182.9,92.8
  Bottom Layer w0.25: v1(-237.634,101.786) -229.627,101.786 -226.5,98.659 v1(-226.5,96) ; v1@-223.1,93.5 v1(-223.075,93.475) -217.7,88.1 -184.2,88.1 -182.925,89.375 v1(-182.925,92.95)
Enable_RS485: R226.2 R318.1 U31.8 | length 94.8
  Top Layer w0.25: U31.8@-239.92,64.059 v1(-238.584,64.059) -238.203,63.678 R318.1@-237.442,63.678 ; v1@-201.5,97.9 -201.471,97.929 -195.581,97.929 -195.552,97.9 v1(-194.3,97.9) ; v1@-193.274,99.574 v1(-190.798,99.574) ; R226.2@-181.609,95.625 -181.6,95.634 v1@-181.6,97.2
  Layer 2 w0.25: v1(-238.584,64.059) -238.584,65.968 -232.204,72.348 -232.204,94.696 -227.2,99.7 v1(-226,99.7) ; v1(-194.3,97.9) -194.3,98.572 v1(-193.298,99.574) ; v1@-190.795,99.6 -188.809,99.6 -186.987,97.778 -186.987,97.439 -186.319,96.771 -183.681,96.771 -183.077,97.375 v1(-181.575,97.375)
  Bottom Layer w0.25: v1(-226,99.7) -216.404,99.7 -215.072,101.033 -207.7,101.033 -206.042,99.375 -206.027,99.375 -204.526,97.874 v1(-201.498,97.874)
F\A\U\L\T\_O\C\_Batt_H1_Buff: C137.2 J12.19 R219.1 | length 66.2
  Top Layer w0.25: R219.1@-184.464,73.291 -184.464,71.264 C137.2@-184.425,71.225 ; v1@-151.675,69.2 -151.663,69.188 -148.112,69.188 v1(-148.1,69.2)
  Layer 2 w0.25: v1(-145.3,59.4) -143.6,61.1 v1@-143.6,64.6
  Bottom Layer w0.25: v1(-184.425,72.1) -183.704,72.821 -171.102,72.821 -170.723,73.2 -155.521,73.2 v1@-151.586,69.265 ; v1(-148.1,69.2) -146.4,69.2 -143.575,66.375 v1(-143.575,64.675) ; v1(-145.3,59.4) -138.044,59.4 -134.534,55.89 J12.19@-134.445,55.89
  other v1: -151.675,69.175
F\A\U\L\T\_O\C\_Batt_H2_Buff: C130.2 J12.14 R223.1 | length 66
  Top Layer w0.25: R223.1@-182.686,73.291 -182.686,71.036 C130.2@-182.575,70.925 ; v1(-151.3,59.4) -148.77,59.4 -148.645,59.275 v1(-148.575,59.275) ; v1(-143.5,52.5) -143.5,51.641 -143,51.141 -134.114,51.141 J12.14@-130.635,54.62
  Layer 2 w0.25: v1@-148.5,59.2 -143.5,54.2 v1(-143.5,52.5)
  Bottom Layer w0.25: v1(-182.725,72.1) -180.1,72.1 -178.737,70.738 -175.738,70.738 -169.129,64.129 -167.904,64.129 -166.375,62.6 -163.666,62.6 -161.266,60.2 -152.1,60.2 v1(-151.3,59.4)
F\A\U\L\T\_O\C\_Batt_L1_Buff: C231.2 J12.21 R221.1 | length 64
  Top Layer w0.25: R221.1@-183.525,77.35 -183.5,77.325 v1(-183.5,76.05) ; v1(-176.925,76.075) -176.925,75 C231.2@-176.9,74.975
  Layer 2 w0.25: v1(-147.6,61.7) -147.626,61.674 -147.626,59.826 -146.484,58.684 v1@-145.316,58.684
  Bottom Layer w0.25: v1(-183.5,76.05) -181.825,74.375 -178.625,74.375 v1@-176.95,76.05 ; v1(-176.925,76.075) -175.504,74.654 -174.602,74.654 -174.295,74.961 -173.709,74.961 -172.449,73.7 -154.9,73.7 -147.9,66.7 -147.9,62 v1(-147.6,61.7) ; v1(-145.3,58.6) -138.425,58.6 J12.21@-135.715,55.89
F\A\U\L\T\_O\C\_Batt_L2_Buff: C131.2 J12.16 R225.1 | length 70.4
  Top Layer w0.25: v1(-181.725,76.1) R225.1@-181.725,77.125 ; C131.2@-174.975,74.925 -175.05,75 v1(-175.05,76.1) -174.646,76.504 -172.756,76.504 -165.3,69.048 v1@-165.3,67.2 ; v1(-163.775,63.475) -163.775,60.575 -163.2,60 v1(-149,60) ; v1(-142.5,52.5) -142.5,51.687 -142.354,51.541 -134.984,51.541 J12.16@-131.905,54.62
  Layer 2 w0.25: v1(-149,60) -148.951,59.951 -148.503,59.951 -142.5,53.948 v1(-142.5,52.5)
  Bottom Layer w0.25: v1(-181.725,76.1) -180.825,75.2 -179.4,75.2 -177.996,76.604 -175.554,76.604 -175.125,76.175 v1@-175.05,76.175 ; v1(-165.375,67.175) -164.5,66.3 -164.5,64.2 v1(-163.775,63.475)
F\A\U\L\T\_O\C\_Boost1_Buff: C135.2 J12.15 R227.1 | length 58.5
  Top Layer w0.25: R227.1@-180.908,73.291 -180.908,73.3 -180.895,73.314 -180.895,72.495 -180.5,72.1 -179.2,72.1 -179,71.9 -179,71.3 C135.2@-178.9,71.2 ; C135.2@-178.9,71.1 -177.864,71.1 -177.614,70.85 -173.15,70.85 v1@-172.4,71.6 ; v1(-146.9,61.2) v1(-145.3,61.2)
  Bottom Layer w0.25: v1(-172.475,71.575) -159.675,71.575 -156.24,68.14 -155.853,68.14 -155.706,67.993 -155.706,67.535 -149.017,60.845 -147.707,60.845 -147.352,61.2 v1(-146.9,61.2) ; v1(-145.3,61.2) -138.008,61.2 -135.887,59.079 -134.779,59.079 -132.159,56.459 -132.159,56.379 -131.905,56.125 J12.15@-131.905,55.89
F\A\U\L\T\_O\C\_Boost2_Buff: C136.2 J12.17 R217.1 | length 72.8
  Top Layer w0.25: C136.2@-188.4,71.1 -188.2,70.9 v1(-187.3,70.9) ; v1(-185.225,76.025) R217.1@-185.225,77.375 ; v1(-151.4,60.6) -147.753,60.6 -147.453,60.3 v1@-145.4,60.3
  Layer 2 w0.25: v1(-187.3,70.9) -183.8,67.4 -165.898,67.4 -165.594,67.704 -163.08,67.704 -162.916,67.541 -162.709,67.541 v1(-162.375,67.875)
  Bottom Layer w0.25: v1(-187.3,70.9) -187.3,73.95 v1(-185.225,76.025) ; v1(-162.375,67.875) -162.375,61.875 -161.1,60.6 v1(-151.4,60.6) ; v1(-145.3,60.3) -137.674,60.3 -133.264,55.89 J12.17@-133.175,55.89
F\A\U\L\T\_O\C\_S1: C37.2 R31.1 R204.2 | length 82.5
  Top Layer w0.25: v1(-198,93) -198,91.929 C37.2@-197.997,91.926 R204.2@-196.219,91.926 -196.051,91.926 R204.2@-195.975,91.85 ; v1@-131.9,112.4 -131.7,112.6 R31.1@-130.7,112.6
  Layer 2 w0.25: v1(-197.5,97.4) -195.6,99.3 v1@-195.4,99.3 ; v1@-161.9,112.3 v1(-132,112.3)
  Bottom Layer w0.25: v1(-198,93) -197.5,93.5 v1(-197.5,97.4) ; v1@-195.369,99.5 -195.3,99.569 -195.3,102.502 -192.702,105.1 -182.048,105.1 -181.869,104.921 -169.552,104.921 -164.494,109.979 -164.196,109.979 v1(-161.825,112.35)
  other v1: -195.325,99.45
F\A\U\L\T\_O\C\_S1_init: R32.2 U6.4 | length 1.6
  Top Layer w0.25: R32.2@-104.7,110.8 -103.175,110.8 U6.4@-103.125,110.75
F\A\U\L\T\_O\C\_S2: C56.2 R68.2 R203.1 | length 80.2
  Top Layer w0.25: R203.1@-193.69,73.325 -193.69,71.29 C56.2@-193.525,71.125 ; v1@-149.7,84.1 -148.1,85.7 -148.1,93.7 -146.371,95.429 R68.2@-145.014,95.429
  Layer 2 w0.25: v1(-188.7,76) -189.329,76.629 -191.819,76.629 -192.577,75.871 -194.619,75.871 -194.929,76.181 -194.929,76.619 -191.609,79.939 v1(-187.811,79.939) ; v1@-187.75,80 -187.761,80.011 -187.761,80.059 -187.75,80.07 -187.75,80.25 -185.6,82.4 -154.777,82.4 -153.102,84.075 v1(-149.775,84.075)
  Bottom Layer w0.25: v1(-193.725,72.15) -189.85,72.15 -188.7,73.3 v1(-188.7,76)
F\A\U\L\T\_O\C\_S2_init: R67.1 U25.4 | length 27.3
  Top Layer w0.25: R67.1@-141.046,94.628 -139.061,94.628 -138.633,94.2 v1(-138.6,94.2) ; v1(-137,94.2) -136.4,94.2 -135.521,95.079 -134.227,95.079 -134.219,95.071 -133.781,95.071 -133.773,95.079 -132.921,95.079 -132.2,95.8 -117.4,95.8 -116.879,95.279 U25.4@-114.801,95.279
  Bottom Layer w0.25: v1(-138.6,94.2) v1(-137,94.2)
F\A\U\L\T\_O\C\_S3: C83.2 R65.1 R206.2 | length 214.8
  Top Layer w0.25: C83.2@-195.582,95.598 R206.2@-193.827,95.598 ; R206.2@-193.65,95.55 v1(-193.65,96.8) ; v1(-168.5,91.866) -168.5,91.816 -157.293,80.609 v1(-157.293,80.559) ; R65.1@-32,85.2 -31.9,85.1 -31.9,84.025 v1@-31.925,84
  Bottom Layer w0.25: v1(-193.65,96.8) -191.25,94.4 -190.166,94.4 -190.141,94.375 -174.375,94.375 -171.879,91.879 -168.513,91.879 v1(-168.5,91.866) ; v1@-157.35,80.609 -155.591,78.85 -153.85,78.85 -146.829,71.829 -144.581,71.829 -132.758,60.006 -132.55,60.006 -132.404,60.152 -132.404,60.369 -132.094,60.679 -120.169,60.679 -120.019,60.829 -117.881,60.829 -116.952,59.9 -109.476,59.9 -108.026,58.45 -100.55,58.45 -88.6,46.5 -50.775,46.5 -31.1,66.175 -31.1,83.125 v1(-31.9,83.925)
F\A\U\L\T\_O\C\_S3_init: R66.2 U13.4 | length 1.5
  Top Layer w0.25: R66.2@-53.5,97.6 -53.45,97.65 U13.4@-53.45,99.125
F\A\U\L\T\_O\C\_S4: C92.2 R205.1 R239.2 | length 49.2
  Top Layer w0.25: R205.1@-191.83,77.289 -191.089,77.289 -190.8,77 -190.8,73.425 -191,73.225 C92.2@-191.625,73.225 ; v1@-156.6,89.6 -155.385,89.6 R239.2@-155.309,89.523
  Layer 2 w0.25: v1(-163.1,85) -162.075,85 -157.5,89.575 v1(-156.475,89.575)
  Bottom Layer w0.25: v1(-190.8,76.1) -188.996,77.904 -175.356,77.904 -174.298,76.846 -171.193,76.846 -171.093,76.946 -170.655,76.946 -170.555,76.846 -168.952,76.846 -164.027,81.771 -164.027,81.793 -163.717,82.103 -163.695,82.103 -163.1,82.698 v1(-163.1,85)
F\A\U\L\T\_O\C\_S4_init: R238.1 U26.4 | length 203.3
  Top Layer w0.25: R238.1@-157.341,84.189 -157.341,82.841 -157.046,82.546 -154.346,82.546 -146.216,74.416 -137.784,74.416 v1@-137.65,74.55 ; v1(-115.1,63.75) -114.15,62.8 -114.15,61.35 v1(-114.9,60.6) ; v1@-33.925,115.25 -33.9,115.275 -33.9,116.525 U26.4@-33.925,116.55
  Bottom Layer w0.25: v1(-137.65,74.475) -133.448,74.475 -132.498,73.525 -130.783,73.525 -128.558,71.3 -118.566,71.3 -116.704,69.438 -116.704,65.354 v1(-115.1,63.75) ; v1(-114.9,60.6) -101.7,60.6 -89.4,48.3 -50.975,48.3 -32.6,66.675 -32.6,89.926 -32.629,89.955 -32.629,113.979 v1(-33.9,115.25)
F\A\U\L\T\_O\C\_S5: C36.2 R28.1 R207.2 | length 83.1
  Top Layer w0.25: v1(-194.6,93) -194.2,92.6 C36.2@-194.2,91.85 ; C36.2@-194.116,91.826 R207.2@-192.338,91.826 -192.249,91.826 R207.2@-192.2,91.875 ; v1@-132.1,114 -131.93,114 -131.805,114.125 R28.1@-130.7,114.125
  Layer 2 w0.25: v1(-195.8,97.4) -195.091,98.109 -195.091,98.936 -194.383,99.644 v1(-194.383,99.679) ; v1(-194.4,101.6) -192.8,103.2 -190.55,103.2 -190,103.75 -188.653,103.75 -188.103,103.2 -171.702,103.2 -162.354,112.548 -162.354,112.569 -162.044,112.879 -162.023,112.879 -160.623,114.279 -143.824,114.279 -143.045,113.5 -132.695,113.5 -132.095,114.1 v1(-132.025,114.1)
  Bottom Layer w0.25: v1(-195.8,97.4) -195.8,94.2 v1(-194.6,93) ; v1(-194.4,101.6) -194.391,101.591 -194.391,99.688 v1(-194.383,99.679)
F\A\U\L\T\_O\C\_S5_init: R29.2 U7.4 | length 1.5
  Top Layer w0.25: R29.2@-108.8,117.75 U7.4@-107.275,117.75
F\A\U\L\T\_O\C\_S6: C82.2 R63.1 R208.2 | length 203.4
  Top Layer w0.25: v1(-192.85,97.65) -191.825,97.65 C82.2@-191.8,97.675 ; C82.2@-191.75,97.525 -191.699,97.474 R208.2@-191.699,95.576 ; v1(-167.675,91.9) -167.675,91.83 -167.546,91.701 -167.546,91.646 v1(-157.1,81.2) ; v1@-33.25,80.7 -33.225,80.725 -33.225,81.925 R63.1@-33.25,81.95
  Bottom Layer w0.25: v1@-192.85,97.675 v1(-192.85,97.65) -189.975,94.775 -173.073,94.775 -171.048,92.75 -168.525,92.75 v1(-167.675,91.9) ; v1(-157.1,81.2) -155.15,79.25 -153.625,79.25 -146.604,72.229 -137.406,72.229 -130.998,65.821 -118.648,65.821 -114.227,61.4 -101.3,61.4 -89.9,50 -52,50 -33.225,68.775 v1(-33.225,80.6)
F\A\U\L\T\_O\C\_S6_init: R64.2 U14.4 | length 1.6
  Top Layer w0.25: U14.4@-60.5,87.9 -60.4,88 -59.05,88 R64.2@-58.95,87.9
F\A\U\L\T\_S1: C245.2 R237.2 U2.46 U6.1 | length 21.9
  Top Layer w0.25: U6.1@-100.3,108.9 -100.1,108.9 -99.925,108.725 -99.925,108.646 -99.779,108.5 C245.2@-98.6,108.5 R237.2@-98.6,107.15 ; v1@-98.625,105.925 -98.6,105.95 R237.2@-98.6,107 ; v1(-94.504,103.382) -94.455,103.332 -93.93,103.332 -93.635,103.038 v1@-92.312,103.038
  Layer 1 w0.25: v1(-98.6,105.85) -98.15,105.85 -97.621,106.379 -96.379,106.379 -95.85,105.85 -94.75,104.75 -94.75,103.657 -94.504,103.411 v1(-94.504,103.382) ; v1@-92.3,103.075 -92.3,103.045 -92.151,102.896 -92.121,102.896 -87.175,97.95 v1(-87.175,97.2)
  Bottom Layer w0.25: U2.46@-87.475,96.375 -87.45,96.4 -87.45,96.855 -87.175,97.13 v1(-87.175,97.2)
  other v1: -92.35,103.025
F\A\U\L\T\_S2_init: C253.2 R335.2 U8.46 U25.1 | length 16.4
  Top Layer w0.25: U25.1@-112.051,93.379 -112.043,93.371 -111.399,93.371 -111.17,93.6 v1(-111.1,93.6) -111.051,93.551 -111.051,93.222 -110.9,93.071 -110.204,93.071 C253.2@-110.15,93.125 R335.2@-110.15,91.725 ; C253.2@-110.262,93.013 -110.2,92.95 C253.2@-110.2,92.925
  Layer 2 w0.25: v1(-111.1,93.6) -110.203,93.6 -107.324,96.479 -105.781,96.479 -105.552,96.25 -102.052,96.25 -101.225,97.077 v1(-101.225,97.125)
  Bottom Layer w0.25: U8.46@-101.225,96.25 -101.242,96.267 -101.242,97.108 v1(-101.225,97.125)
F\A\U\L\T\_S3: C249.2 R331.2 U9.46 U13.1 | length 22
  Top Layer w0.25: C249.2@-52.4,103.7 R331.2@-50.9,103.7 -50.725,103.525 v1(-50.725,102.45) ; C249.2@-52.4,103.729 -52.331,103.659 -52.331,102.971 -52.059,102.7 -51.8,102.7 -51.6,102.5 -51.6,102.1 U13.1@-51.672,102.172
  Layer 1 w0.25: v1(-60.6,112.325) -59.975,112.95 -58.75,112.95 -58.1,112.3 -58.1,111 -50.868,103.768 -50.868,102.69 -50.708,102.531 v1@-50.631,102.531
  Bottom Layer w0.25: U9.46@-60.785,113.275 -60.685,113.175 -60.685,112.455 -60.6,112.37 v1@-60.6,112.3
F\A\U\L\T\_S4_init: C254.2 R336.2 U15.46 U26.1 | length 20.6
  Top Layer w0.25: C254.2@-38.4,118.4 -38.35,118.45 U26.1@-36.675,118.45 -36.55,118.45 U26.1@-36.525,118.475 ; C254.2@-38.35,118.65 -38.4,118.7 R336.2@-38.4,119.8 -37.522,119.8 -37.372,119.65 v1@-37.325,119.65
  Layer 2 w0.25: v1(-46.75,112.1) -46.171,111.521 -42.204,111.521 -37.318,116.407 -37.318,119.782 v1@-37.283,119.817
  Bottom Layer w0.25: U15.46@-46.785,113.275 -46.768,113.258 -46.768,112.057 v1@-46.775,112.05
  other v1: -37.3,119.8
F\A\U\L\T\_S5: C247.2 R329.2 U4.46 U7.1 | length 22
  Top Layer w0.25: U7.1@-104.45,115.85 -103.025,115.85 C247.2@-102.947,115.928 ; R329.2@-102.825,114.325 R329.2@-102.8,114.35 ; R329.2@-102.775,114.5 -102.817,114.542 C247.2@-102.817,115.798 -102.825,115.807 -102.825,115.928 -102.662,115.928 -101.965,116.625 -100.679,116.625 -100.358,116.303 -97.754,113.7 -95.8,113.7 v1(-95.3,113.2)
  Layer 1 w0.25: v1(-95.3,113.2) -93.95,111.85 -88.727,111.85 -88.102,111.225 v1(-87.4,111.225)
  Bottom Layer w0.25: U4.46@-87.465,110.225 -87.433,110.258 -87.433,111.217 v1@-87.4,111.25
F\A\U\L\T\_S6: C48.2 R33.2 U11.46 U14.1 | length 12.9
  Top Layer w0.25: C48.2@-64.9,90.9 -64.55,90.55 -63.35,90.55 -63.2,90.4 U14.1@-63.2,89.9 ; C48.2@-64.9,91 -64.9,92.1 v1(-64.9,93.5)
  Layer 1 w0.25: v1(-64.9,93.5) -63.763,94.637 -62.063,94.637 -60.975,95.725 v1(-60.975,97.825) v1@-60.975,97.85
  Bottom Layer w0.25: v1(-60.975,97.825) -60.975,97.895 -60.775,98.095 U11.46@-60.775,98.8
GND_ISO_COMM: C1.1 C198.1 C205.2 C207.2 C211.1 C220.1 C223.1 C224.2 C225.2 C226.1 C227.2 C228.2 C236.1 FB18.2 FB23.1 FB23.2 J15.3 J15.5 J15.6 J15.10 J15.11 J17.5 J17.10 J17.11 R126.1 U30.15 U30.16 U30.17 U31.11 U31.13 U31.15 | length 43.6
  Top Layer w0.25: FB18.2@-259.652,106.371 -259.652,106.973 -259.506,107.119 C211.1@-259.506,108.058 -259.439,108.125 v1@-258.2,108.125 ; FB23.1@-258.75,65.85 FB23.2@-258.75,66.65 -258.7,66.65 -258.37,66.98 -258.18,66.98 -258,66.8 C228.2@-256.8,66.8 ; C207.2@-257.982,91.618 C207.2@-257.489,91.125 ; C207.2@-257.525,91.5 -257.434,91.591 -255.984,91.591 -255.675,91.9 C198.1@-255.675,92.769 ; C225.2@-256.9,62.632 -256.795,62.737 C228.2@-256.795,66.705 ; C228.2@-256.719,66.861 -256.465,66.607 C226.1@-254.179,66.607 C227.2@-252.311,66.607 ; C220.1@-256.247,95.749 -255.274,95.749 v1@-255.25,95.725 ; C236.1@-255.946,56.782 -255.9,56.736 v1@-255.9,55.7 ; C198.1@-255.696,92.769 C198.1@-255.675,92.769 ; C198.1@-255.675,92.95 C198.1@-255.675,92.769 ; -254.8,64 -254.7,63.9 C223.1@-254.7,61.727 ; C223.1@-254.3,61.7 C224.2@-252.1,61.7 -252,61.6 v1(-251.1,61.6) -251.059,61.559 -250.159,61.559 U31.15@-250.1,61.5 ; C205.2@-252.431,92.769 C198.1@-255.675,92.769 ; C205.2@-252.394,92.796 -252.359,92.761 -252.359,90.441 -252.4,90.4 v1@-252.352,90.352 ; C227.2@-252.136,66.634 -250.141,66.634 U31.11@-250.075,66.7 ; v1@-251.775,100.75 -251.593,100.75 -251.581,100.762 U30.15@-250.156,100.762 U30.16@-250.156,99.492 -250.156,98.356 U30.17@-250.15,98.35 ; v1@-251.5,77.525 -251.485,77.54 C1.1@-248.416,77.54 ; v1(-251.1,64.1) -251.08,64.079 -249.64,64.079 U31.13@-249.62,64.059
  other v1: -255.974,55.717 -251.138,66.634 -251.575,77.575 -252.323,90.428 -255.275,95.725 -251.725,100.8 -258.225,108.15
IAC_F\A\U\L\T\: C113.2 R88.2 R229.1 | length 54.6
  Top Layer w0.25: R88.2@-193,109.3 -193,106.1 v1(-191.2,104.3) ; v1@-189.7,102.9 -189.625,102.825 -189.625,102.567 v1(-188.674,101.617) ; v1(-185.4,97.4) -184.871,97.929 -181.381,97.929 -180.274,96.822 v1(-180.274,89.517) ; v1@-179.9,76.1 -179.9,77.243 R229.1@-179.892,77.251 ; v1(-173,75.9) -173,75.3 C113.2@-172.8,75.1
  Layer 2 w0.25: v1@-186.4,99.443 -186.425,99.418 -186.425,99.185 -186.4,99.16 -186.4,98.4 v1(-185.4,97.4) ; v1@-176.5,78.6 -177.3,78.6 v1(-179.9,76) -179.1,75.2 -173.7,75.2 v1(-173,75.9)
  Bottom Layer w0.25: v1(-191.2,104.3) -191.179,104.3 -189.769,102.89 -189.697,102.89 v1@-189.687,102.9 ; v1@-188.6,101.6 -188.6,101.543 v1(-186.474,99.417) ; v1@-180.2,89.5 -180.2,82.243 v1(-176.574,78.617)
  other v1: -189.674,102.817
IAC_O\C\: C108.2 R87.2 R231.1 | length 60.7
  Top Layer w0.25: v1(-187.2,108.2) R87.2@-187.2,109.2 ; v1(-185.474,102.617) -184.607,101.75 -179.984,101.75 -175.745,97.511 -175.745,95.397 -172.894,92.546 -171.351,92.546 -169.1,90.295 v1@-169.1,88.6 ; R231.1@-179.085,73.5 R231.1@-178.876,73.291 -178.876,72.476 -178.699,72.299 -178.299,72.299 v1(-178.25,72.25) ; C108.2@-177.1,71.6 -177.875,71.6 -178.201,71.926 -178.201,72.131 -178.25,72.18 v1(-178.25,72.25) ; v1@-171.7,74.545 -171.7,73.336 -172.586,72.45 -177.724,72.45 -177.875,72.299 -178.201,72.299 v1(-178.25,72.25) ; v1@-170.8,76.6 -170.774,76.626 v1(-170.774,77.517)
  Layer 2 w0.25: v1(-187.2,108.2) -187.2,107.048 -186,105.848 v1@-186,104.1 ; v1(-171.774,74.417) -171.774,75.426 v1@-170.8,76.4 ; v1@-170.8,77.5 -169.957,78.343 v1(-168.303,78.343)
  Bottom Layer w0.25: v1(-186.074,104.117) -185.4,103.443 v1@-185.4,102.6 ; v1(-169.074,88.617) -167.608,87.151 -167.608,78.992 v1@-168.2,78.4
  other v1: -170.874,76.417
IAC_REF: C112.2 R86.1 R181.1 | length 36.5
  Top Layer w0.25: v1(-215.8,94.1) -214.726,94.1 C112.2@-214.698,94.072 -214.698,93.223 -214.45,92.975 -214.171,92.975 -214.025,92.829 -214.025,92.4 -213.875,92.25 R181.1@-213.825,92.25 ; v1(-191.1,108.2) R86.1@-191.1,109.2
  Layer 2 w0.25: v1(-206.8,97.8) -206.8,98.698 -204.498,101 -196.802,101 -191.1,106.702 v1@-191.1,108.1
  Bottom Layer w0.25: v1(-215.8,94.1) -211.565,94.1 -207.665,98 -207.07,98 -206.87,97.8 v1(-206.8,97.8)
IAC_sense: C107.2 R83.2 R180.1 | length 32
  Top Layer w0.25: R180.1@-213.1,95.7 -212.975,95.825 C107.2@-212.975,97.375 -212.95,97.4 v1@-210.5,97.4 ; v1(-189.1,106.7) R83.2@-189.1,109.2
  Layer 2 w0.25: v1(-210.574,97.417) -206.391,101.6 v1@-201.6,101.6
  Bottom Layer w0.25: v1(-201.674,101.617) -199.133,101.617 -194.15,106.6 v1@-189.2,106.6
IDC_sense: C9.2 R2.2 R175.2 | length 194.3
  Top Layer w0.25: R175.2@-217.738,95.598 -217.725,95.611 v1(-217.725,96.65) ; C9.2@-85,24.7 -83.375,24.7 R2.2@-83.325,24.65 ; v1(-83.95,23.55) -83.881,23.619 -83.481,23.619 -83.325,23.775 R2.2@-83.325,24.35
  Layer 2 w0.25: v1(-206.075,98.675) -204.15,100.6 -191.214,100.6 -189.668,102.146 -187.49,102.146 -187.432,102.088 -174.212,102.088 v1@-173.8,102.5 ; v1@-168.6,102.5 -168.575,102.475 v1(-160.475,102.475) ; v1@-135.7,103.4 -133.52,101.22 -130.547,101.22 -128.624,99.297 -128.624,98.724 v1(-128.575,98.675) ; v1@-120.7,91.936 -120.7,86.238 -121.2,85.738 -121.2,82.6 -111.8,73.2 -111.8,66.2 v1(-99.1,53.5)
  Bottom Layer w0.25: v1(-217.725,96.65) -215.4,96.65 -215.254,96.796 -215.254,97.094 -214.944,97.404 -214.346,97.404 -213.05,98.7 v1@-206,98.7 ; v1@-173.799,102.446 -173.77,102.475 v1(-168.675,102.475) ; v1@-160.4,102.5 -159.371,103.529 -147.609,103.529 -147.455,103.375 v1(-135.775,103.375) ; v1(-128.575,98.675) -128.575,97.475 -124.045,92.945 -121.745,92.945 v1@-120.7,91.9 ; v1(-99.1,53.5) -91.5,45.9 -91.5,30.5 -84.579,23.579 -83.979,23.579 v1(-83.95,23.55)
  other v1: -120.8,91.9 -173.798,102.474
IN_PWM_S1: C13.2 R9.2 U2.45 | length 40.1
  Top Layer w0.25: R9.2@-112.075,119.6 -111.975,119.5 -110.95,119.5 v1@-110.875,119.575 ; v1(-94.5,107.525) -94.5,106.325 v1@-92.85,104.675 ; C13.2@-88.475,98.45 -88.425,98.4 -88.425,97.7 v1(-88,97.275)
  Layer 1 w0.25: v1(-110.85,119.5) -110.825,119.5 -110.575,119.75 -103.275,119.75 -94.5,110.975 v1(-94.5,107.525) ; v1@-92.781,104.575 -92.83,104.575 -92.874,104.531 -92.874,104.418 -92.879,104.414 -92.879,102.806 -92.569,102.496 -92.287,102.496 -88,98.209 v1(-88,97.275)
  Bottom Layer w0.25: U2.45@-88.175,96.5 -88.029,96.646 -88.029,97.246 v1(-88,97.275)
  other v1: -92.825,104.65
IN_PWM_S3: C59.2 R19.2 U9.45 | length 30.5
  Top Layer w0.25: v1(-59.673,111.921) -59.624,111.872 -59.624,111.749 -58.875,111 C59.2@-58.8,111 ; v1(-48.7,92.975) -48.7,91.825 -47.829,90.954 -47.179,90.954 R19.2@-47.1,90.875
  Layer 1 w0.25: v1(-59.673,111.921) -58.586,110.834 -58.5,110.834 -51.268,103.603 -51.268,102.245 -49.923,100.9 -48.595,100.9 -48.449,100.754 -48.449,97.2 -48.729,96.919 -48.729,94.241 -48.721,94.233 -48.721,93.598 -48.581,93.458 -48.581,93.164 -48.7,93.045 v1(-48.7,92.975)
  Bottom Layer w0.25: U9.45@-60.1,113.1 -60.035,113.035 -60.035,112.353 -59.673,111.991 v1(-59.673,111.921)
IN_PWM_S5: C26.2 R8.2 U4.45 | length 32.7
  Top Layer w0.25: R8.2@-112.075,121 -112.025,120.95 -110.95,120.95 v1@-110.875,121.025 ; C26.2@-88.8,112.7 -88.672,112.828 v1(-88.004,112.828)
  Layer 1 w0.25: v1(-110.85,120.95) -93.45,120.95 -87.825,115.325 -87.825,114.201 -88.004,114.022 v1(-88.004,112.828)
  Bottom Layer w0.25: U4.45@-88.115,110.225 U4.45@-88.015,110.325 ; U4.45@-88.115,110.325 -88.115,111.26 -88.004,111.371 v1(-88.004,112.828)
IN_PWM_S6: C71.2 R18.2 U11.45 | length 24.9
  Top Layer w0.25: v1(-59.925,97.8) -59.925,97.75 -59.65,97.475 -59.65,96.7 C71.2@-59.6,96.65 ; v1(-45.125,89.35) -44.3,89.35 R18.2@-44.275,89.325
  Layer 1 w0.25: v1@-59.925,97.775 -59.974,97.726 -59.974,93.549 -58.604,92.179 -58.604,92.131 -58.294,91.821 -58.246,91.821 -56.925,90.5 -50.173,90.5 -48.944,89.271 -47.481,89.271 -46.452,90.3 -46.075,90.3 v1(-45.125,89.35)
  Bottom Layer w0.25: U11.45@-60.15,98.75 -60.15,98.095 -59.925,97.87 v1(-59.925,97.8)
NetC6_1: C6.1 C7.1 FB1.2 U1.6 | length 5.5
  Top Layer w0.25: FB1.2@-84.75,27.975 -81.7,27.975 C6.1@-81.675,27.95 ; C6.1@-81.45,28.025 -80.096,28.025 -79.95,27.879 -79.95,27.16 U1.6@-79.883,27.093
NetC8_1: C8.1 R3.2 U1.3 | length 3.4
  Top Layer w0.25: R3.2@-77.95,22.825 -77.983,22.858 U1.3@-77.983,24.343 -76.093,24.343 C8.1@-76.075,24.325
NetC8_2: C8.2 R4.2 U1.4 | length 4.2
  Top Layer w0.25: R4.2@-78,28.725 -77.983,28.708 -77.983,27.308 U1.4@-77.875,27.2 ; U1.4@-77.983,27.093 -77.851,27.225 -76.65,27.225 -76.3,26.875 -76.3,26.35 -76.15,26.2 C8.2@-76.125,26.2
NetC14_2: C14.2 R10.2 U2.50 | length 3.8
  Top Layer w0.25: v1@-84.9,97.275 -84.9,97.4 -85.2,97.7 R10.2@-85.2,98.425 -85.125,98.35 C14.2@-83.675,98.35
  Bottom Layer w0.25: v1(-84.875,97.15) -84.888,97.137 -84.888,96.288 U2.50@-84.85,96.25
NetC15_1: C15.1 D4.1 U2.40 U2.41 | length 8.6
  Top Layer w0.25: C15.1@-91.341,94.5 -91.341,95.659 -90,97 -90,98.884 -90.146,99.03 -90.175,99.03 -90.3,99.155 D4.1@-90.3,99.43
  Top Layer w0.5: v1(-92.575,94.575) -91.675,94.575 C15.1@-91.6,94.5
  Bottom Layer w0.25: v1(-92.575,94.575) -92.537,94.537 -91.298,94.537 U2.41@-91.26,94.5 U2.40@-91.26,93.85
NetC18_2: C18.2 C22.1 FB2.2 U3.6 U3.7 | length 6.7
  Top Layer w0.25: FB2.2@-130.475,106.425 FB2.2@-130.375,106.425 C18.2@-128.475,106.425 -127.737,106.425 -127.562,106.25 U3.7@-124.45,106.25 ; U3.7@-124.45,106.325 U3.6@-124.45,106.9
NetC21_1: C21.1 R12.2 R15.1 U3.33 U3.34 | length 7.6
  Top Layer w0.25: U3.33@-114.5,108.25 U3.34@-114.5,108.85 -114.45,108.8 -113.375,108.8 -113.05,108.475 R12.2@-110.675,108.475 ; R12.2@-110.675,108.425 -109.4,108.425 -109.05,108.775 R15.1@-109.05,109.975
NetC23_2: C23.2 R13.2 R14.2 U3.4 | length 10
  Top Layer w0.25: R14.2@-133.875,106.825 R13.2@-132.2,106.825 ; R13.2@-132.175,106.825 -131.25,106.825 -129.875,108.2 C23.2@-128.55,108.2 -126.9,108.2 ; -126.975,108.2 U3.4@-124.45,108.2
NetC25_2: C25.2 U4.51 | length 3.7
  Top Layer w0.25: v1@-82.9,111.375 -82.175,111.375 -81.75,111.8 -81.75,112.675 C25.2@-81.7,112.725
  Bottom Layer w0.25: U4.51@-84.225,110.75 -83.654,111.321 -83.054,111.321 v1(-83.025,111.35)
NetC27_2: C27.2 R30.2 U4.50 | length 4.5
  Top Layer w0.25: v1@-84.7,111.3 -85.25,111.85 R30.2@-85.25,112.725 -83.65,112.725 C27.2@-83.6,112.675
  Bottom Layer w0.25: U4.50@-84.865,110.225 -84.765,110.325 -84.765,111.165 -84.655,111.275 v1@-84.6,111.275
  other v1: -84.625,111.375
NetC28_1: C28.1 D10.1 U4.40 U4.41 | length 6
  Top Layer w0.25: D10.1@-93.7,110.73 -93.6,110.63 -93.6,110 -92.95,109.35 -92.95,109.095 -92.625,108.77 v1(-92.625,108.7) ; C28.1@-91.2,108.5 C28.1@-91.07,108.37
  Top Layer w0.5: v1(-92.625,108.7) C28.1@-91.316,108.7
  Bottom Layer w0.25: v1(-92.625,108.7) -92.612,108.713 -91.238,108.713 U4.41@-91.225,108.7
  Bottom Layer w0.5: U4.40@-91.225,108.075 U4.41@-91.225,108.7
NetC29_2: C29.2 R16.2 R105.2 U19.4 | length 12.8
  Top Layer w0.25: C29.2@-165.45,93 -165.2,93.25 C29.2@-165.185,93.25 ; U19.4@-165.085,94.426 -165.085,93.35 C29.2@-165.185,93.25 ; R16.2@-164.2,97.5 -163.25,97.5 -162.5,96.75 -162.5,96.01 -162.354,95.864 -161.664,95.864 R105.2@-161.6,95.8 -161.454,95.946 -161.454,96.55 v1(-160.875,96.55) ; v1(-163.5,93.25) C29.2@-165.185,93.25
  Layer 1 w0.25: v1(-163.5,93.25) -160.875,95.875 v1(-160.875,96.55)
NetC32_2: C32.2 R32.1 U5.2 | length 17.3
  Top Layer w0.25: U5.2@-116.675,116.613 -116.113,116.613 -115.066,115.566 -115.066,114.691 -114.404,114.029 -113.979,114.029 C32.2@-113.85,113.9 ; v1(-105.75,109.125) -104.7,109.125 R32.1@-104.65,109.075
  Layer 1 w0.25: v1(-115.075,115.1) -109.1,109.125 -105.825,109.125 v1@-105.8,109.1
